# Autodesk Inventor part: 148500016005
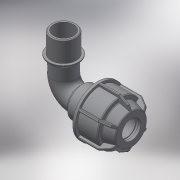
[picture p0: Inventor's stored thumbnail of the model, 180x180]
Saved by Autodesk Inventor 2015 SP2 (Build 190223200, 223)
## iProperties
Created: 2017-08
Part Number: 148500016005
Material: Generic
Description: PLASSON L.14 90° ELBOW MALE ADAPTOR (SILVER) 16-1/2"
Document SubType Name: Modeling
Designer: KIM
Density: 1 g/cm^3
Appearance: Default
Author: KIM
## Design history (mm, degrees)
derived "148500.ipt"
feature "Solid1::148500.ipt"
feature "Solid2::148500.ipt"
tag "TaggingFeature1"
body "Solid1"
body "Solid2"
other parameters: "d1" = 16, "d2" = 43, "d4" = 15 deg, "d5" = 28.38, "d6" = 9.3654, "d10" = 42, "d16" = 16.32, "d17" = 2.15, "d22" = 25.6, "d24" = 2.15, "d25" = 37.8, "d26" = 31.5, "d27" = 2.15, "d28" = 135 deg, "d29" = 1.29, "d31" = 0.8, "d46" = 150 deg, "d49" = 2.1, "d50" = 0, "d58" = 0.48, "d61" = 360 deg, "d63" = 14.4, "d94" = 44, "d96" = 23.0505, "d97" = 17, "d98" = 16.764, "d99" = 19.59292, "d100" = 135 deg, "d108" = 0.8, "d112" = 22.1, "d113" = 57, "d114" = 43.86, "d115" = 19.59292, "d116" = 45 deg, "d117" = 0, "d118" = 0, "d119" = 20.955, "d120" = 17, "d121" = 25.146, "d122" = 17.85, "d123" = 1, "d_" = 16, "R_" = 20.955, "E_" = 42, "A_" = 57, "l_" = 43, "l_2" = 17, "A_1" = 44
